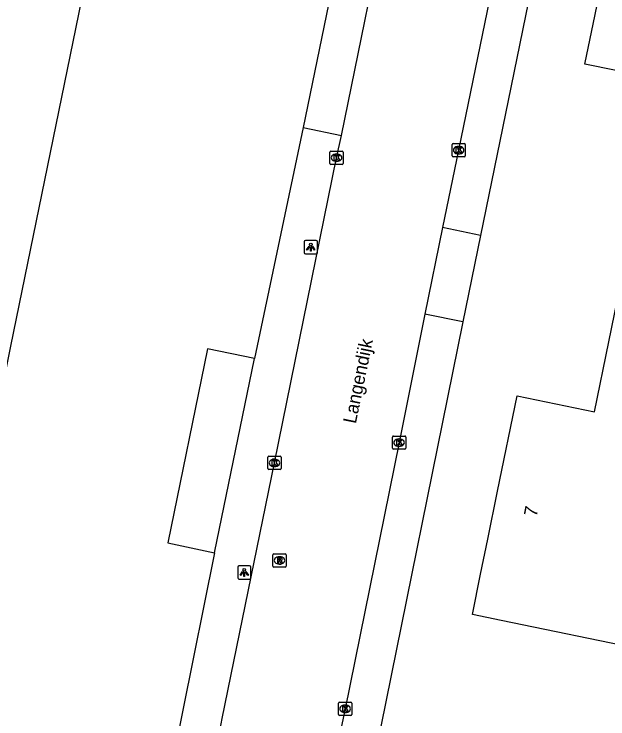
# Model space of a CAD drawing. Extents: x 157692 to 159670, y 381454 to 383289.
# Drawn here: x 158074.3 to 158119.2, y 381883.9 to 381937.1 of the extents above; entities that cross this region are included whole.
import ezdxf

# ---------------------------------------------------------------- set-up
doc = ezdxf.new("R2010")
doc.units = 0
for name, color, linetype in [('IMGEO_Kolk', 7, 'Continuous'), ('IMGEO_Lichtpunt', 7, 'Continuous'), ('IMGEO_Openbare_ruimte_label', 7, 'Continuous'), ('IMGEO_Pand', 7, 'Continuous'), ('IMGEO_Pand_nummerreeks', 7, 'Continuous'), ('IMGEO_Rijbaan_lokaal_gesloten', 7, 'Continuous'), ('IMGEO_Rioolput', 7, 'Continuous'), ('IMGEO_Voetpad_open', 7, 'Continuous')]:
    doc.layers.add(name, color=color, linetype=linetype)

msp = doc.modelspace()

# ---------------------------------------------------------------- linework, layer by layer
at = {"layer": 'IMGEO_Kolk'}
for p, q in [((158107.403, 381926.378), (158107.403, 381927.23)), ((158107.478, 381927.304), (158108.33, 381927.304)), ((158107.891, 381927.084), (158107.916, 381927.084)), ((158108.404, 381927.23), (158108.404, 381926.378)), ((158098.179, 381925.805), (158098.179, 381926.657)), ((158098.254, 381926.731), (158099.106, 381926.731)), ((158098.667, 381926.511), (158098.692, 381926.511)), ((158099.18, 381926.657), (158099.18, 381925.805)), ((158107.914, 381926.524), (158107.889, 381926.524)), ((158098.69, 381925.951), (158098.665, 381925.951)), ((158108.33, 381926.304), (158107.478, 381926.304)), ((158099.106, 381925.731), (158098.254, 381925.731)), ((158102.975, 381905.228), (158103.827, 381905.228)), ((158102.9, 381904.302), (158102.9, 381905.154)), ((158103.388, 381905.008), (158103.413, 381905.008)), ((158103.901, 381905.154), (158103.901, 381904.302)), ((158103.827, 381904.228), (158102.975, 381904.228)), ((158103.411, 381904.448), (158103.386, 381904.448)), ((158093.492, 381902.773), (158093.492, 381903.625)), ((158093.567, 381903.699), (158094.419, 381903.699)), ((158094.493, 381903.625), (158094.493, 381902.773)), ((158093.98, 381903.479), (158094.005, 381903.479)), ((158094.419, 381902.699), (158093.567, 381902.699)), ((158094.003, 381902.919), (158093.978, 381902.919)), ((158098.823, 381884.215), (158098.823, 381885.067)), ((158098.898, 381885.141), (158099.75, 381885.141)), ((158099.824, 381885.067), (158099.824, 381884.215)), ((158099.311, 381884.921), (158099.336, 381884.921)), ((158099.75, 381884.141), (158098.898, 381884.141)), ((158099.334, 381884.361), (158099.309, 381884.361))]:
    msp.add_line(p, q, dxfattribs=at)
for points in [[(158107.403, 381926.378), (158107.403, 381927.23)], [(158107.478, 381927.304), (158108.33, 381927.304)], [(158107.724, 381927.004), (158107.847, 381927.004), (158107.847, 381926.853), (158107.977, 381927.004), (158108.141, 381927.004), (158107.995, 381926.853), (158108.148, 381926.604), (158107.996, 381926.604), (158107.911, 381926.768), (158107.847, 381926.701), (158107.847, 381926.604), (158107.724, 381926.604), (158107.724, 381927.004)], [(158108.404, 381927.23), (158108.404, 381926.378)], [(158098.179, 381925.805), (158098.179, 381926.657)], [(158098.254, 381926.731), (158099.106, 381926.731)], [(158099.18, 381926.657), (158099.18, 381925.805)], [(158098.5, 381926.431), (158098.623, 381926.431), (158098.623, 381926.28), (158098.753, 381926.431), (158098.917, 381926.431), (158098.771, 381926.28), (158098.924, 381926.031), (158098.772, 381926.031), (158098.687, 381926.195), (158098.623, 381926.128), (158098.623, 381926.031), (158098.5, 381926.031), (158098.5, 381926.431)], [(158108.33, 381926.304), (158107.478, 381926.304)], [(158099.106, 381925.731), (158098.254, 381925.731)], [(158102.975, 381905.228), (158103.827, 381905.228)], [(158102.9, 381904.302), (158102.9, 381905.154)], [(158103.221, 381904.928), (158103.344, 381904.928), (158103.344, 381904.777), (158103.474, 381904.928), (158103.638, 381904.928), (158103.492, 381904.777), (158103.645, 381904.528), (158103.493, 381904.528), (158103.408, 381904.692), (158103.344, 381904.625), (158103.344, 381904.528), (158103.221, 381904.528), (158103.221, 381904.928)], [(158103.901, 381905.154), (158103.901, 381904.302)], [(158103.827, 381904.228), (158102.975, 381904.228)], [(158093.492, 381902.773), (158093.492, 381903.625)], [(158093.567, 381903.699), (158094.419, 381903.699)], [(158094.493, 381903.625), (158094.493, 381902.773)], [(158093.813, 381903.399), (158093.936, 381903.399), (158093.936, 381903.248), (158094.066, 381903.399), (158094.23, 381903.399), (158094.084, 381903.248), (158094.237, 381902.999), (158094.085, 381902.999), (158094, 381903.163), (158093.936, 381903.096), (158093.936, 381902.999), (158093.813, 381902.999), (158093.813, 381903.399)], [(158094.419, 381902.699), (158093.567, 381902.699)], [(158098.823, 381884.215), (158098.823, 381885.067)], [(158098.898, 381885.141), (158099.75, 381885.141)], [(158099.824, 381885.067), (158099.824, 381884.215)], [(158099.144, 381884.841), (158099.267, 381884.841), (158099.267, 381884.69), (158099.397, 381884.841), (158099.561, 381884.841), (158099.415, 381884.69), (158099.568, 381884.441), (158099.416, 381884.441), (158099.331, 381884.605), (158099.267, 381884.538), (158099.267, 381884.441), (158099.144, 381884.441), (158099.144, 381884.841)], [(158099.75, 381884.141), (158098.898, 381884.141)]]:
    msp.add_lwpolyline(points, dxfattribs=at)
for centre, start, end in [((158107.48, 381927.228), 91.552, 178.448), ((158107.48, 381927.228), 91.552, 178.448), ((158108.328, 381927.228), 1.552, 88.448), ((158108.328, 381927.228), 1.552, 88.448), ((158098.256, 381926.655), 91.552, 178.448), ((158098.256, 381926.655), 91.552, 178.448), ((158099.104, 381926.655), 1.552, 88.448), ((158099.104, 381926.655), 1.552, 88.448), ((158107.48, 381926.38), 181.552, 268.448), ((158107.48, 381926.38), 181.552, 268.448), ((158108.328, 381926.38), 271.552, 358.448), ((158108.328, 381926.38), 271.552, 358.448), ((158098.256, 381925.807), 181.552, 268.448), ((158098.256, 381925.807), 181.552, 268.448), ((158099.104, 381925.807), 271.552, 358.448), ((158099.104, 381925.807), 271.552, 358.448), ((158102.977, 381905.152), 91.552, 178.448), ((158102.977, 381905.152), 91.552, 178.448), ((158103.825, 381905.152), 1.552, 88.448), ((158103.825, 381905.152), 1.552, 88.448), ((158102.977, 381904.304), 181.552, 268.448), ((158102.977, 381904.304), 181.552, 268.448), ((158103.825, 381904.304), 271.552, 358.448), ((158103.825, 381904.304), 271.552, 358.448), ((158093.569, 381903.623), 91.552, 178.448), ((158093.569, 381903.623), 91.552, 178.448), ((158094.417, 381903.623), 1.552, 88.448), ((158094.417, 381903.623), 1.552, 88.448), ((158093.569, 381902.775), 181.552, 268.448), ((158093.569, 381902.775), 181.552, 268.448), ((158094.417, 381902.775), 271.552, 358.448), ((158094.417, 381902.775), 271.552, 358.448), ((158098.9, 381885.065), 91.552, 178.448), ((158098.9, 381885.065), 91.552, 178.448), ((158099.748, 381885.065), 1.552, 88.448), ((158099.748, 381885.065), 1.552, 88.448), ((158098.9, 381884.217), 181.552, 268.448), ((158098.9, 381884.217), 181.552, 268.448), ((158099.748, 381884.217), 271.552, 358.448), ((158099.748, 381884.217), 271.552, 358.448)]:
    msp.add_arc(centre, 0.0765, start, end, dxfattribs=at)
for centre, major_axis, ratio, start_param, end_param in [((158107.89, 381926.804), (-0.387, 0.002), 0.722429, 4.712389, 7.853982), ((158107.915, 381926.804), (-0.39, 0.002), 0.717154, 1.570796, 4.712389), ((158098.666, 381926.231), (-0.387, 0.002), 0.722429, 4.712389, 7.853982), ((158098.691, 381926.231), (-0.39, 0.002), 0.717154, 1.570796, 4.712389), ((158103.387, 381904.728), (-0.387, 0.002), 0.722429, 4.712389, 7.853982), ((158103.412, 381904.728), (-0.39, 0.002), 0.717154, 1.570796, 4.712389), ((158093.979, 381903.199), (-0.387, 0.002), 0.722429, 4.712389, 7.853982), ((158094.004, 381903.199), (-0.39, 0.002), 0.717154, 1.570796, 4.712389), ((158099.31, 381884.641), (-0.387, 0.002), 0.722429, 4.712389, 7.853982), ((158099.335, 381884.641), (-0.39, 0.002), 0.717154, 1.570796, 4.712389)]:
    msp.add_ellipse(centre, major_axis=major_axis, ratio=ratio, start_param=start_param, end_param=end_param, dxfattribs=at)
at = {"layer": 'IMGEO_Lichtpunt'}
for p, q in [((158096.235, 381919.885), (158096.235, 381919.078)), ((158096.235, 381919.885), (158096.235, 381919.078)), ((158097.137, 381919.98), (158096.329, 381919.98)), ((158097.137, 381919.98), (158096.329, 381919.98)), ((158097.231, 381919.078), (158097.231, 381919.885)), ((158097.231, 381919.078), (158097.231, 381919.885)), ((158096.329, 381918.984), (158097.137, 381918.984)), ((158096.329, 381918.984), (158097.137, 381918.984)), ((158091.212, 381895.338), (158091.212, 381894.531)), ((158091.212, 381895.338), (158091.212, 381894.531)), ((158092.114, 381895.433), (158091.306, 381895.433)), ((158092.114, 381895.433), (158091.306, 381895.433)), ((158092.208, 381894.531), (158092.208, 381895.338)), ((158092.208, 381894.531), (158092.208, 381895.338)), ((158091.306, 381894.437), (158092.114, 381894.437)), ((158091.306, 381894.437), (158092.114, 381894.437))]:
    msp.add_line(p, q, dxfattribs=at)
for points in [[(158096.609, 381919.549), (158096.648, 381919.521), (158096.46, 381919.259), (158096.422, 381919.286), (158096.609, 381919.549)], [(158096.821, 381919.521), (158096.859, 381919.548), (158097.046, 381919.286), (158097.007, 381919.258), (158096.821, 381919.521)], [(158096.711, 381919.501), (158096.758, 381919.501), (158096.758, 381919.179), (158096.711, 381919.179), (158096.711, 381919.501)], [(158091.586, 381895.002), (158091.625, 381894.974), (158091.437, 381894.712), (158091.399, 381894.739), (158091.586, 381895.002)], [(158091.688, 381894.954), (158091.735, 381894.954), (158091.735, 381894.632), (158091.688, 381894.632), (158091.688, 381894.954)], [(158091.798, 381894.974), (158091.836, 381895.001), (158092.023, 381894.739), (158091.984, 381894.711), (158091.798, 381894.974)]]:
    msp.add_lwpolyline(points, dxfattribs=at)
for centre in [(158096.734, 381919.683), (158091.711, 381895.136)]:
    msp.add_circle(centre, 0.0994, dxfattribs=at)
for centre, start, end in [((158096.329, 381919.885), 90, 180), ((158096.329, 381919.885), 90, 180), ((158097.137, 381919.885), 0, 90), ((158097.137, 381919.885), 0, 90), ((158096.329, 381919.078), 180, 270), ((158096.329, 381919.078), 180, 270), ((158097.137, 381919.078), 270, 0), ((158097.137, 381919.078), 270, 360), ((158091.306, 381895.338), 90, 180), ((158091.306, 381895.338), 90, 180), ((158092.114, 381895.338), 0, 90), ((158092.114, 381895.338), 0, 90), ((158091.306, 381894.531), 180, 270), ((158091.306, 381894.531), 180, 270), ((158092.114, 381894.531), 270, 0), ((158092.114, 381894.531), 270, 360)]:
    msp.add_arc(centre, 0.0946, start, end, dxfattribs=at)
at = {"layer": 'IMGEO_Pand'}
for points in [[(157924.37, 382007.696), (157951.127, 382002.234), (157958.802, 382040.19), (157964.374, 382039.087), (157964.027, 382037.391), (157940.465, 381922.271), (158070.771, 381895.776), (158074.09, 381912.003), (158079.649, 381939.178), (158094.319, 382010.896), (158099.527, 382036.361), (158101.614, 382035.935), (158102.387, 382039.726), (158100.3, 382040.151), (158125.007, 382160.95), (158000, 382186.53)], [(158155.923, 381925.462), (158122.302, 381932.306), (158117.426, 381933.299), (158119.903, 381945.169), (158118.785, 381945.383), (158118.546, 381945.191)], [(158131.806, 381903.957), (158125.129, 381905.329), (158121.859, 381889.092), (158111.126, 381891.312), (158108.952, 381891.762), (158109.544, 381894.79), (158110.094, 381897.451), (158110.842, 381901.073), (158112.312, 381908.256), (158118.152, 381907.045), (158120.337, 381917.624), (158122.497, 381928.081), (158136.166, 381925.258)], [(158092.48, 381911.08), (158088.925, 381911.805), (158085.937, 381897.157), (158089.467, 381896.422)], [(158089.467, 381896.422), (158092.48, 381911.08)]]:
    msp.add_lwpolyline(points, dxfattribs=at)
at = {"layer": 'IMGEO_Rijbaan_lokaal_gesloten'}
for points in [[(158116.186, 381967.321), (158116.023, 381966.537), (158112.225, 381947.864), (158107.903, 381926.804), (158106.687, 381920.975)], [(158099.043, 381927.911), (158102.858, 381946.545)], [(158082.429, 381846.881), (158083.809, 381853.599), (158084.29, 381855.738), (158089.883, 381883.116), (158090.046, 381883.911), (158093.994, 381903.198), (158098.681, 381926.231), (158099.043, 381927.911)], [(158106.687, 381920.975), (158105.353, 381914.424)], [(158105.353, 381914.424), (158103.401, 381904.728), (158099.323, 381884.642), (158098.778, 381882.055), (158098.248, 381879.541)]]:
    msp.add_lwpolyline(points, dxfattribs=at)
at = {"layer": 'IMGEO_Rioolput'}
for p, q in [((158093.871, 381895.413), (158093.871, 381896.265)), ((158093.946, 381896.339), (158094.798, 381896.339)), ((158094.359, 381896.119), (158094.384, 381896.119)), ((158094.872, 381896.265), (158094.872, 381895.413)), ((158094.798, 381895.339), (158093.946, 381895.339)), ((158094.382, 381895.559), (158094.357, 381895.559))]:
    msp.add_line(p, q, dxfattribs=at)
for points in [[(158093.871, 381895.413), (158093.871, 381896.265)], [(158093.946, 381896.339), (158094.798, 381896.339)], [(158094.872, 381896.265), (158094.872, 381895.413)], [(158094.46, 381896.037), (158094.208, 381896.039), (158094.208, 381895.639)], [(158094.208, 381895.639), (158094.332, 381895.639), (158094.332, 381895.801), (158094.343, 381895.801)], [(158094.386, 381895.958), (158094.332, 381895.958), (158094.332, 381895.877)], [(158094.332, 381895.877), (158094.384, 381895.877)], [(158094.39, 381895.772), (158094.461, 381895.639), (158094.601, 381895.639), (158094.536, 381895.765)], [(158094.798, 381895.339), (158093.946, 381895.339)]]:
    msp.add_lwpolyline(points, dxfattribs=at)
for centre, radius, start, end in [((158093.948, 381896.263), 0.0765, 91.552, 178.448), ((158093.948, 381896.263), 0.0765, 91.552, 178.448), ((158094.796, 381896.263), 0.0765, 1.552, 88.448), ((158094.796, 381896.263), 0.0765, 1.552, 88.448), ((158094.342, 381895.748), 0.0533, 26.0293, 88.6989), ((158094.368, 381896.066), 0.19, 274.7715, 282.9687), ((158094.392, 381895.862), 0.0964, 77.0061, 93.1865), ((158094.406, 381895.919), 0.0378, 276.6634, 79.6772), ((158094.459, 381895.927), 0.109, 350.3612, 89.416), ((158094.457, 381895.927), 0.112, 277.5842, 350.9817), ((158094.441, 381895.712), 0.108, 29.5134, 73.7905), ((158093.948, 381895.415), 0.0765, 181.552, 268.448), ((158093.948, 381895.415), 0.0765, 181.552, 268.448), ((158094.796, 381895.415), 0.0765, 271.552, 358.448), ((158094.796, 381895.415), 0.0765, 271.552, 358.448)]:
    msp.add_arc(centre, radius, start, end, dxfattribs=at)
for centre, major_axis, ratio, start_param, end_param in [((158094.358, 381895.839), (-0.387, 0.002), 0.722429, 4.712389, 7.853982), ((158094.383, 381895.839), (-0.39, 0.002), 0.717154, 1.570796, 4.712389)]:
    msp.add_ellipse(centre, major_axis=major_axis, ratio=ratio, start_param=start_param, end_param=end_param, dxfattribs=at)
at = {"layer": 'IMGEO_Voetpad_open'}
for points in [[(158119.054, 381966.712), (158111.645, 381930.552), (158109.555, 381920.351)], [(158099.982, 381947.1), (158096.169, 381928.502)], [(158096.169, 381928.502), (158092.48, 381911.08)], [(158096.169, 381928.502), (158099.043, 381927.911)], [(158109.555, 381920.351), (158106.687, 381920.975)], [(158109.555, 381920.351), (158108.214, 381913.847)], [(158108.214, 381913.847), (158105.353, 381914.424)], [(158108.214, 381913.847), (158101.637, 381881.433), (158103.57, 381880.897)], [(158089.467, 381896.422), (158087.078, 381884.542), (158081.414, 381856.37), (158079.616, 381847.467)]]:
    msp.add_lwpolyline(points, dxfattribs=at)

# ---------------------------------------------------------------- texts
at = {"layer": 'IMGEO_Openbare_ruimte_label'}
msp.add_text('Langendijk', height=1, rotation=78.4093, dxfattribs=at).set_placement((158100.135, 381906.112))
at = {"layer": 'IMGEO_Pand_nummerreeks'}
msp.add_text('7', height=1, rotation=78.4858, dxfattribs=at).set_placement((158113.792, 381899.084))

doc.saveas('drawing.dxf')
